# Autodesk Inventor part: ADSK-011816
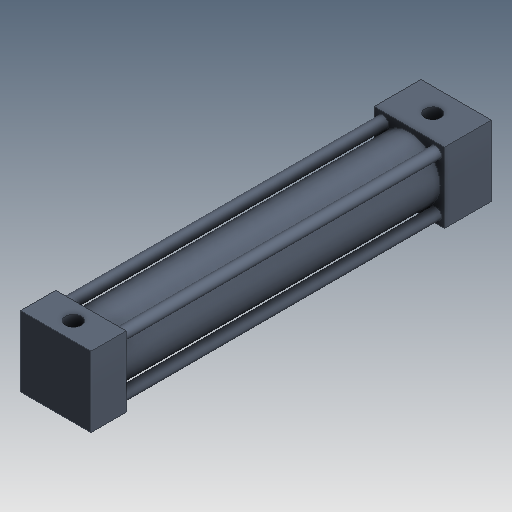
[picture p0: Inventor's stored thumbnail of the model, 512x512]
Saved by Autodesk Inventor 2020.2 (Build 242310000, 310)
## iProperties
Created: 1999-12
Part Number: ADSK-011816
Document SubType Name: Modeling
Designer: glanglot
Material: Générique
Density: 1 g/cm^3
Appearance: Métal - Plomb
Mass: 235.208 g
Surface Area: 430.896 cm^2
Volume: 235.208 cm^3
Control State: 0
Master: False
Checked Out: False
Shininess: 0.0
Length Units: 11272
Angle Units: 11279
Time Units: 11290
Mass Units: 11286
Length Display Precision: 3
Angle Display Precision: 2
Compacted: True
Dimensions: 1,5x8,5x1,5 in
Mass: 0,519 lb
VLT_Material: Generic
Density: 0.0
Volumn: 0.0
Area: 0.0
PropertySet Name: Model Information
Author: glanglot
Revision Number: -
Title: ADSK-011816
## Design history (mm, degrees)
node "Extrusion1" dims "d2" = 25.4, "d3" = 0
node "Extrusion2" dims "d7" = 172.339, "d8" = 0
node "Extrusion3" dims "d9" = 19.05, "d10" = 0
node "Hole1" dims "d14" = 8.6106, "d15" = 9.525, "d16" = 6.35, "d17" = 60 deg, "d18" = 12.7, "d19" = 118 deg
node "Extrusion4" dims "d32" = 12.7, "d33" = 0
workplane "Work Plane1"
node "Solide1"
node "Corps solides"
node "Corps surfaciques"
sketch "Sketch1"
  geometry: L1 (-40.587, -7.206)-(-2.487, -7.206) reference; L2 (-2.487, -7.206)-(-2.487, -45.306); L3 (-2.487, -45.306)-(-40.587, -45.306); L4 (-40.587, -45.306)-(-40.587, -7.206) reference
  constraints: 8 end point, 2 horizontal, 2 parallel, 1 perpendicular, 1 vertical
  dimensions: "d0" = 38.1 distance of L1.start L1.end; "d1" = 38.1 distance of L3.end L1.start (= d0)
sketch "Sketch2"
  geometry: L1 (-40.587, -7.206)-(-2.487, -7.206) reference; L2 (-40.587, -45.306)-(-40.587, -7.206) reference; C1 r 16.669 at (-21.537, -26.256)
  constraints: 1 centre point
  dimensions: "d4" = 19.05 distance from line of C1.centre L2; "d5" = 19.05 distance from line of C1.centre L1 (= d4); "d6" = 33.3375 diameter of C1
sketch "Sketch4"
  geometry: L1 (-19.05, 19.05)-(19.05, 19.05) reference; L2 (-19.05, -19.05)-(-19.05, 19.05) reference; L3 (19.05, -19.05)-(-19.05, -19.05) reference; L4 (19.05, 19.05)-(19.05, -19.05) reference
sketch "Sketch5"
  geometry: L1 (38.1, 0)-(0, 0) reference; L2 (0, 0)-(0, -25.4) reference; L3 (0, -216.789)-(38.1, -216.789) reference; 2 further points
  constraints: 1 vertical alignment
  dimensions: "d11" = 19.05 distance from line of point (19.05, -12.7) L2; "d12" = 12.7 distance from line of point (19.05, -12.7) L1; "d13" = 9.525 distance from line of L3 point (19.05, -207.264)
sketch "Sketch6"
  geometry: L1 (-40.587, -7.206)-(-2.487, -7.206) reference; L2 (-40.587, -45.306)-(-40.587, -7.206) reference; L3 (-2.487, -45.306)-(-40.587, -45.306) reference; L4 (-2.487, -7.206)-(-2.487, -45.306) reference; C1 r 3.175 at (-35.825, -11.968); C2 r 3.175 at (-7.25, -11.968); C3 r 3.175 at (-7.25, -40.543); C4 r 3.175 at (-35.825, -40.543)
  constraints: 4 centre point
  dimensions: "d20" = 6.35 diameter of C1; "d21" = 4.7625 distance from line of L2 C1.centre; "d22" = 4.7625 distance from line of C1.centre L1 (= d21); "d23" = 6.35 diameter of C2 (= d20); "d24" = 4.7625 distance from line of L1 C2.centre (= d21); "d25" = 4.7625 distance from line of L4 C2.centre (= d21); "d26" = 4.7625 distance from line of L2 C4.centre (= d21); "d27" = 4.7625 distance from line of C4.centre L3 (= d21); "d28" = 6.35 diameter of C4 (= d20); "d29" = 6.35 diameter of C3 (= d20); "d30" = 4.7625 distance from line of L4 C3.centre (= d21); "d31" = 4.7625 distance from line of L3 C3.centre (= d21)
other parameters: "d34" = -19.05
